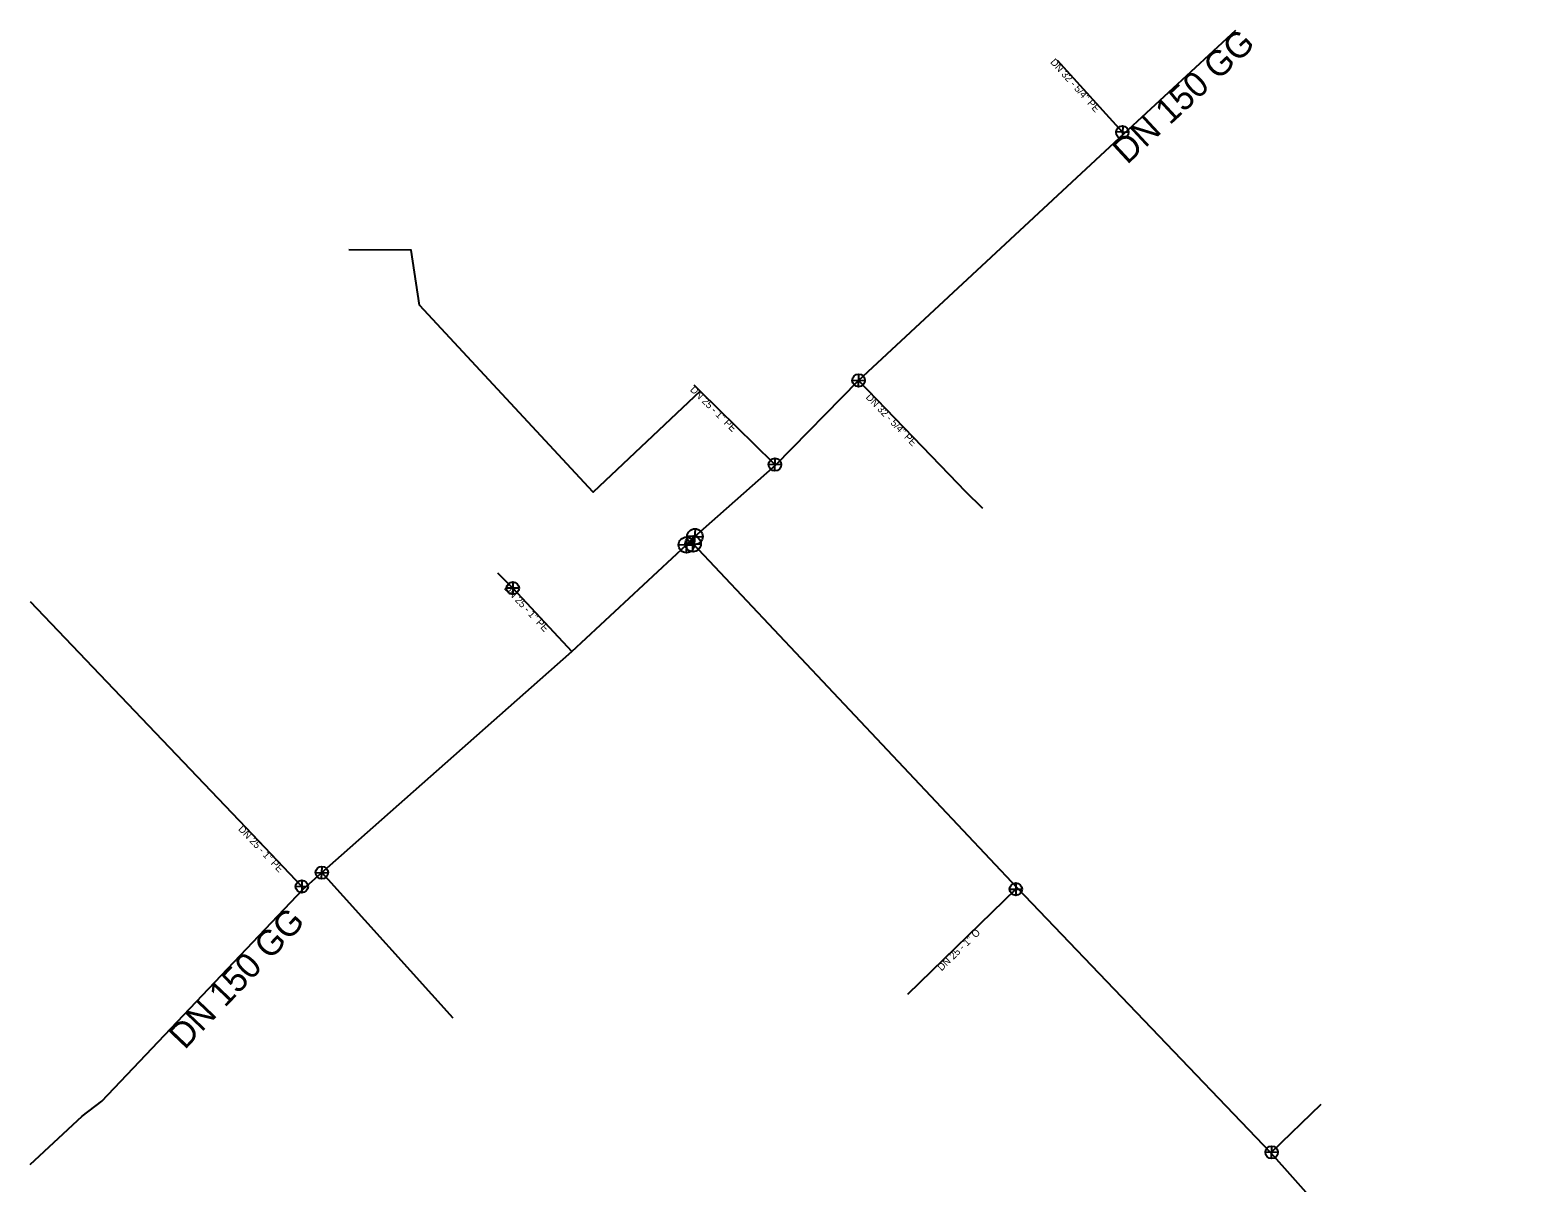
# Model space of a CAD drawing. Extents: x -446879 to -446633, y -1113504 to -1113264.
# Drawn here: x -446878.7 to -446782.8, y -1113337.6 to -1113264.3 of the extents above; entities that cross this region are included whole.
import ezdxf

# ---------------------------------------------------------------- set-up
doc = ezdxf.new("R2010")
doc.units = 0
for name, color, linetype in [('_pripojka_prevzato_z_dokumentace_', 7, 'Continuous'), ('_pripojka_priblizne_', 7, 'Continuous'), ('_voda_smvak_prevzato_z_dokumentace_', 7, 'Continuous'), ('Default', 7, 'Continuous'), ('MoLevel 27', 7, 'Continuous'), ('MoLevel 32', 7, 'Continuous'), ('MoLevel 46', 7, 'Continuous'), ('MoLevel 53', 7, 'Continuous')]:
    doc.layers.add(name, color=color, linetype=linetype)

# ---------------------------------------------------------------- blocks, each defined once
blk = doc.blocks.new('_uzaver_')
at = {"layer": 'Default'}
for p, q in [((-0.000035, -0.000035), (0.000035, 0.000035)), ((0.000035, -0.000035), (-0.000035, 0.000035))]:
    blk.add_line(p, q, dxfattribs=at)
for radius in [0.00005, 0.0000025]:
    blk.add_circle((0, 0), radius, dxfattribs=at)
blk = doc.blocks.new('_uzaver_pripojka_')
at = {"layer": 'Default'}
for p, q in [((-0.000035, -0.000035), (0.000035, 0.000035)), ((0.000035, -0.000035), (-0.000035, 0.000035))]:
    blk.add_line(p, q, dxfattribs=at)
for radius in [0.00005, 0.0000025]:
    blk.add_circle((0, 0), radius, dxfattribs=at)

msp = doc.modelspace()

# ---------------------------------------------------------------- linework, layer by layer
at = {"layer": '_pripojka_prevzato_z_dokumentace_'}
msp.add_line((-446878.661, -1113300.67), (-446864.96, -1113315.053), dxfattribs=at)
at = {"layer": '_pripojka_priblizne_'}
for p, q in [((-446825.999, -1113286.62), (-446820.245, -1113292.595)), ((-446836.061, -1113287.299), (-446836.448, -1113286.919)), ((-446860.117, -1113317.919), (-446851.793, -1113327.158)), ((-446799.74, -1113335.7), (-446796.589, -1113332.646))]:
    msp.add_line(p, q, dxfattribs=at)
for points in [[(-446809.12, -1113270.92), (-446809.23, -1113270.84), (-446813.347, -1113266.275)], [(-446836.061, -1113287.299), (-446842.877, -1113293.719), (-446853.91, -1113281.839), (-446854.442, -1113278.34), (-446858.398, -1113278.325)], [(-446831.28, -1113292.01), (-446831.4, -1113291.88), (-446836.061, -1113287.299)], [(-446820.246, -1113292.595), (-446819.22, -1113293.66), (-446818.128, -1113294.752)], [(-446848.947, -1113298.846), (-446847.98, -1113299.83), (-446844.23, -1113303.85)], [(-446864.96, -1113315.053), (-446861.39, -1113318.8), (-446861.3, -1113318.97)], [(-446815.912, -1113318.898), (-446816, -1113318.97), (-446822.895, -1113325.665)]]:
    msp.add_lwpolyline(points, dxfattribs=at)
at = {"layer": '_voda_smvak_prevzato_z_dokumentace_'}
for p, q in [((-446836.94, -1113297.08), (-446836.674, -1113296.822)), ((-446836.674, -1113296.822), (-446836.4, -1113296.55)), ((-446836.52, -1113297.01), (-446836.674, -1113296.822))]:
    msp.add_line(p, q, dxfattribs=at)
for points in [[(-446836.4, -1113296.55), (-446831.28, -1113292.01), (-446826, -1113286.62), (-446809.12, -1113270.92), (-446802.02, -1113264.35)], [(-446878.661, -1113336.464), (-446875.35, -1113333.4), (-446874.11, -1113332.44), (-446861.3, -1113318.97), (-446859.78, -1113317.62), (-446844.23, -1113303.85), (-446836.94, -1113297.08)], [(-446760.89, -1113377.1), (-446764.33, -1113373.76), (-446767.09, -1113370.6), (-446779.25, -1113357.44), (-446786.03, -1113350.55), (-446788.36, -1113348.05), (-446795.29, -1113340.78), (-446799.77, -1113335.76), (-446815.92, -1113318.89), (-446836.52, -1113297.01)]]:
    msp.add_lwpolyline(points, dxfattribs=at)

# ---------------------------------------------------------------- block references
at = {"layer": 'MoLevel 27'}
for p, xscale, yscale, rotation in [((-446836.94, -1113297.08), 10000.000000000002, 10000.000000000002, -137.12581353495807), ((-446836.52, -1113297.01), 10000, 10000, -46.696699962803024), ((-446836.4, -1113296.55), 10000, 10000, 41.580682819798)]:
    msp.add_blockref('_uzaver_', p, dxfattribs=dict(at, xscale=xscale, yscale=yscale, rotation=rotation))
at = {"layer": 'MoLevel 53'}
for p, xscale, yscale, rotation in [((-446809.23, -1113270.84), 8000, 7999.999999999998, 132.04609959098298), ((-446825.999, -1113286.62), 7999.999999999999, 8000, -46.07945000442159), ((-446831.315, -1113291.973), 7999.999999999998, 8000, 42.9567313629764), ((-446847.98, -1113299.83), 7999.999999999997, 7999.999999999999, 135.27678905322), ((-446860.117, -1113317.919), 7999.999999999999, 7999.999999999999, -47.97986532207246), ((-446861.39, -1113318.8), 7999.999999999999, 7999.999999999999, 133.60859553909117), ((-446816, -1113318.97), 8000.000000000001, 7999.999999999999, -135.75932736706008), ((-446799.74, -1113335.7), 7999.999999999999, 8000.000000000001, 43.72580820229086)]:
    msp.add_blockref('_uzaver_pripojka_', p, dxfattribs=dict(at, xscale=xscale, yscale=yscale, rotation=rotation))

# ---------------------------------------------------------------- texts
at = {"layer": 'MoLevel 32'}
for s, rotation, p in [("DN 32 - 5/4'' PE", 312.0461, (-446813.841, -1113266.407)), ("DN 25 - 1'' PE", 315.50018, (-446836.742, -1113287.251)), ("DN 32 - 5/4'' PE", 313.92056, (-446825.569, -1113287.724)), ("DN 25 - 1'' PE", 313.00983, (-446848.579, -1113299.855)), ("DN 25 - 1'' PE", 313.60742, (-446865.467, -1113315.179)), ("DN 25 - 1'' O", 44.15846, (-446820.722, -1113324.197))]:
    msp.add_text(s, height=0.455, rotation=rotation, dxfattribs=at).set_placement(p)
at = {"layer": 'MoLevel 46'}
for rotation, p in [(42.7797, (-446808.93, -1113272.931)), (46.43863, (-446868.835, -1113329.222))]:
    msp.add_text('DN 150 GG', height=1.6049, rotation=rotation, dxfattribs=at).set_placement(p)

doc.saveas('drawing.dxf')
